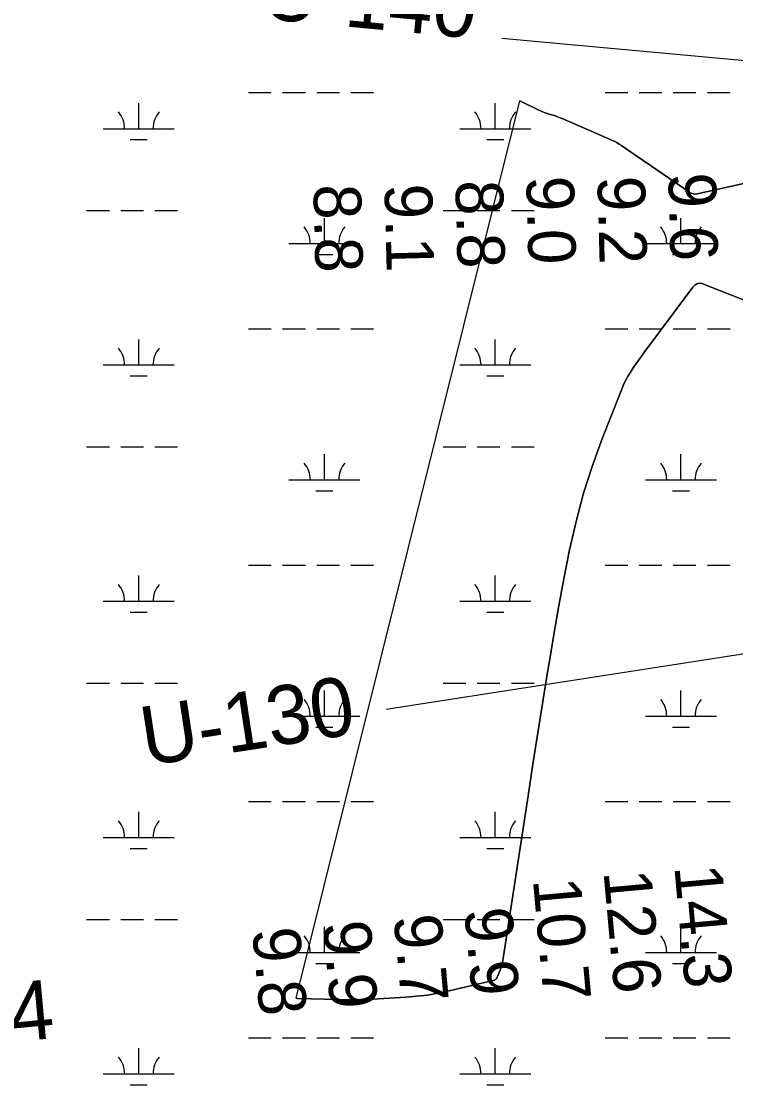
# Model space of a CAD drawing. Extents: x 3535183 to 3573198, y 534952 to 560562.
# Drawn here: x 3550386 to 3551392, y 549415 to 550912 of the extents above; entities that cross this region are included whole.
import ezdxf

# ---------------------------------------------------------------- set-up
doc = ezdxf.new("R2010")
doc.units = 0
for name, color, linetype in [('V-RIVR-RANG', 7, 'Continuous'), ('V-RIVR-RANG-IDEN', 7, 'Continuous'), ('V-TOPO-DPTH', 7, 'Continuous'), ('V-TOPO-MINR', 7, 'Continuous'), ('V-WETL-SWMP', 7, 'Continuous')]:
    doc.layers.add(name, color=color, linetype=linetype)

msp = doc.modelspace()

# ---------------------------------------------------------------- linework, layer by layer
at = {"layer": 'V-RIVR-RANG'}
for p, q in [((3551063.1, 550888.7), (3551959.3, 550806.5)), ((3550900.3, 549943.7), (3551789.6, 550082.1))]:
    msp.add_line(p, q, dxfattribs=at)
at = {"layer": 'V-TOPO-DPTH'}
for points in [[(3551428, 550510.3), (3551344.6, 550543.1), (3551341.1, 550543.7), (3551337.7, 550542.8), (3551334.6, 550540.8), (3551332.1, 550538.1), (3551263.1, 550445.8), (3551258.5, 550439.5), (3551253.9, 550433.1), (3551249.5, 550426.6), (3551245.2, 550420), (3551241.1, 550413.3), (3551237.3, 550406.5), (3551234, 550399.4), (3551230.9, 550392.2), (3551204.9, 550325.7), (3551190.8, 550287), (3551178.2, 550247.9), (3551167.6, 550208.1), (3551158.5, 550168), (3551150.5, 550127.5), (3551142.9, 550086.9), (3551135.8, 550046.3), (3551129, 550005.6), (3551127.8, 549998.8), (3551120.7, 549954.6), (3551113.7, 549910.4), (3551106.8, 549866.2), (3551099.9, 549822), (3551064.2, 549589.9), (3551063.3, 549585.3), (3551062.2, 549580.8), (3551060.6, 549576.4), (3551058.8, 549572.1), (3551055.3, 549564.4), (3551055.1, 549564), (3551053.8, 549562.7), (3551052.5, 549562.2), (3550988.7, 549547.2), (3550973.6, 549544.1), (3550958.4, 549541.4), (3550943.1, 549539.6), (3550927.7, 549538.3), (3550889.2, 549535.9), (3550875.1, 549535.2), (3550861, 549534.8), (3550846.8, 549534.7), (3550832.7, 549534.9), (3550775.1, 549536.5), (3550773.3, 549536.8), (3551088.5, 550800.4)], [(3551088.5, 550800.4), (3551114.2, 550787.8), (3551118.3, 550785.9), (3551122.4, 550784.1), (3551126.7, 550782.7), (3551131, 550781.3), (3551135.3, 550780), (3551139.6, 550778.6), (3551143.8, 550777), (3551148, 550775.3), (3551217.8, 550745.1), (3551221.3, 550743.4), (3551224.8, 550741.6), (3551228.1, 550739.6), (3551231.4, 550737.5), (3551234.7, 550735.3), (3551237.9, 550733), (3551241.1, 550730.8), (3551244.3, 550728.6), (3551327.2, 550671.6), (3551328.4, 550670.8), (3551332.4, 550669.3), (3551335.3, 550669), (3551338.2, 550669.3), (3551424.8, 550688.5)]]:
    msp.add_lwpolyline(points, dxfattribs=at)
at = {"layer": 'V-TOPO-MINR'}
for points in [[(3551424.8, 550688.5), (3551338.2, 550669.3), (3551335.3, 550669), (3551332.4, 550669.3), (3551328.4, 550670.8), (3551327.2, 550671.6), (3551244.3, 550728.6), (3551241.1, 550730.8), (3551237.9, 550733), (3551234.7, 550735.3), (3551231.4, 550737.5), (3551228.1, 550739.6), (3551224.8, 550741.6), (3551221.3, 550743.4), (3551217.8, 550745.1), (3551148, 550775.3), (3551143.8, 550777), (3551139.6, 550778.6), (3551135.3, 550780), (3551131, 550781.3), (3551126.7, 550782.7), (3551122.4, 550784.1), (3551118.3, 550785.9), (3551114.2, 550787.8), (3551088.5, 550800.4)], [(3550773.3, 549536.8), (3550775.1, 549536.5), (3550832.7, 549534.9), (3550846.8, 549534.7), (3550861, 549534.8), (3550875.1, 549535.2), (3550889.2, 549535.9), (3550927.7, 549538.3), (3550943.1, 549539.6), (3550958.4, 549541.4), (3550973.6, 549544.1), (3550988.7, 549547.2), (3551052.5, 549562.2), (3551053.8, 549562.7), (3551055.1, 549564), (3551055.3, 549564.4), (3551058.8, 549572.1), (3551060.6, 549576.4), (3551062.2, 549580.8), (3551063.3, 549585.3), (3551064.2, 549589.9), (3551099.9, 549822), (3551106.8, 549866.2), (3551113.7, 549910.4), (3551120.7, 549954.6), (3551127.8, 549998.8), (3551129, 550005.6), (3551135.8, 550046.3), (3551142.9, 550086.9), (3551150.5, 550127.5), (3551158.5, 550168), (3551167.6, 550208.1), (3551178.2, 550247.9), (3551190.8, 550287), (3551204.9, 550325.7), (3551230.9, 550392.2), (3551234, 550399.4), (3551237.3, 550406.5), (3551241.1, 550413.3), (3551245.2, 550420), (3551249.5, 550426.6), (3551253.9, 550433.1), (3551258.5, 550439.5), (3551263.1, 550445.8), (3551332.1, 550538.1), (3551334.6, 550540.8), (3551337.7, 550542.8), (3551341.1, 550543.7), (3551344.6, 550543.1), (3551428, 550510.3)]]:
    msp.add_lwpolyline(points, dxfattribs=at)
at = {"layer": 'V-WETL-SWMP'}
for p, q in [((3550706.4, 550811.9), (3550738.4, 550811.9)), ((3550754.4, 550811.9), (3550786.4, 550811.9)), ((3550802.4, 550811.9), (3550834.4, 550811.9)), ((3550850.4, 550811.9), (3550882.4, 550811.9)), ((3551208.4, 550811.9), (3551240.4, 550811.9)), ((3551256.4, 550811.9), (3551288.4, 550811.9)), ((3551304.4, 550811.9), (3551336.4, 550811.9)), ((3551352.4, 550811.9), (3551384.4, 550811.9)), ((3550551.9, 550761.2), (3550551.9, 550797.2)), ((3551053.8, 550761.2), (3551053.8, 550797.2)), ((3550501.9, 550761.2), (3550601.9, 550761.2)), ((3551003.8, 550761.2), (3551103.8, 550761.2)), ((3550539.9, 550745.8), (3550563.9, 550745.8)), ((3551041.8, 550745.8), (3551065.8, 550745.8)), ((3550478.4, 550645.8), (3550510.4, 550645.8)), ((3550526.4, 550645.8), (3550558.4, 550645.8)), ((3550574.4, 550645.8), (3550606.4, 550645.8)), ((3550813.3, 550599.3), (3550813.3, 550635.3)), ((3550980.4, 550645.8), (3551012.4, 550645.8)), ((3551028.4, 550645.8), (3551060.4, 550645.8)), ((3551076.4, 550645.8), (3551108.4, 550645.8)), ((3551315.2, 550599.3), (3551315.2, 550635.3)), ((3550763.3, 550599.3), (3550863.3, 550599.3)), ((3551265.2, 550599.3), (3551365.2, 550599.3)), ((3550801.3, 550583.9), (3550825.3, 550583.9)), ((3551303.2, 550583.9), (3551327.2, 550583.9)), ((3550706.4, 550479.3), (3550738.4, 550479.3)), ((3550754.4, 550479.3), (3550786.4, 550479.3)), ((3550802.4, 550479.3), (3550834.4, 550479.3)), ((3550850.4, 550479.3), (3550882.4, 550479.3)), ((3551208.4, 550479.3), (3551240.4, 550479.3)), ((3551256.4, 550479.3), (3551288.4, 550479.3)), ((3551304.4, 550479.3), (3551336.4, 550479.3)), ((3551352.4, 550479.3), (3551384.4, 550479.3)), ((3550551.9, 550428.5), (3550551.9, 550464.5)), ((3551053.8, 550428.5), (3551053.8, 550464.5)), ((3550501.9, 550428.5), (3550601.9, 550428.5)), ((3551003.8, 550428.5), (3551103.8, 550428.5)), ((3550539.9, 550413.1), (3550563.9, 550413.1)), ((3551041.8, 550413.1), (3551065.8, 550413.1)), ((3550478.4, 550313.1), (3550510.4, 550313.1)), ((3550526.4, 550313.1), (3550558.4, 550313.1)), ((3550574.4, 550313.1), (3550606.4, 550313.1)), ((3550980.4, 550313.1), (3551012.4, 550313.1)), ((3551028.4, 550313.1), (3551060.4, 550313.1)), ((3551076.4, 550313.1), (3551108.4, 550313.1)), ((3550813.3, 550266.7), (3550813.3, 550302.7)), ((3551315.2, 550266.7), (3551315.2, 550302.7)), ((3550763.3, 550266.7), (3550863.3, 550266.7)), ((3551265.2, 550266.7), (3551365.2, 550266.7)), ((3550801.3, 550251.2), (3550825.3, 550251.2)), ((3551303.2, 550251.2), (3551327.2, 550251.2)), ((3550706.4, 550146.6), (3550738.4, 550146.6)), ((3550754.4, 550146.6), (3550786.4, 550146.6)), ((3550802.4, 550146.6), (3550834.4, 550146.6)), ((3550850.4, 550146.6), (3550882.4, 550146.6)), ((3551208.4, 550146.6), (3551240.4, 550146.6)), ((3551256.4, 550146.6), (3551288.4, 550146.6)), ((3551304.4, 550146.6), (3551336.4, 550146.6)), ((3551352.4, 550146.6), (3551384.4, 550146.6)), ((3550551.9, 550095.9), (3550551.9, 550131.9)), ((3551053.8, 550095.9), (3551053.8, 550131.9)), ((3550501.9, 550095.9), (3550601.9, 550095.9)), ((3551003.8, 550095.9), (3551103.8, 550095.9)), ((3550539.9, 550080.4), (3550563.9, 550080.4)), ((3551041.8, 550080.4), (3551065.8, 550080.4)), ((3550478.4, 549980.4), (3550510.4, 549980.4)), ((3550526.4, 549980.4), (3550558.4, 549980.4)), ((3550574.4, 549980.4), (3550606.4, 549980.4)), ((3550980.4, 549980.4), (3551012.4, 549980.4)), ((3551028.4, 549980.4), (3551060.4, 549980.4)), ((3551076.4, 549980.4), (3551108.4, 549980.4)), ((3550813.3, 549934), (3550813.3, 549970)), ((3551315.2, 549934), (3551315.2, 549970)), ((3550763.3, 549934), (3550863.3, 549934)), ((3551265.2, 549934), (3551365.2, 549934)), ((3550801.3, 549918.6), (3550825.3, 549918.6)), ((3551303.2, 549918.6), (3551327.2, 549918.6)), ((3550706.4, 549813.9), (3550738.4, 549813.9)), ((3550754.4, 549813.9), (3550786.4, 549813.9)), ((3550802.4, 549813.9), (3550834.4, 549813.9)), ((3550850.4, 549813.9), (3550882.4, 549813.9)), ((3551208.4, 549813.9), (3551240.4, 549813.9)), ((3551256.4, 549813.9), (3551288.4, 549813.9)), ((3551304.4, 549813.9), (3551336.4, 549813.9)), ((3551352.4, 549813.9), (3551384.4, 549813.9)), ((3550551.9, 549763.2), (3550551.9, 549799.2)), ((3551053.8, 549763.2), (3551053.8, 549799.2)), ((3550501.9, 549763.2), (3550601.9, 549763.2)), ((3551003.8, 549763.2), (3551103.8, 549763.2)), ((3550539.9, 549747.7), (3550563.9, 549747.7)), ((3551041.8, 549747.7), (3551065.8, 549747.7)), ((3550478.4, 549647.7), (3550510.4, 549647.7)), ((3550526.4, 549647.7), (3550558.4, 549647.7)), ((3550574.4, 549647.7), (3550606.4, 549647.7)), ((3550980.4, 549647.7), (3551012.4, 549647.7)), ((3551028.4, 549647.7), (3551060.4, 549647.7)), ((3551076.4, 549647.7), (3551108.4, 549647.7)), ((3550813.3, 549601.3), (3550813.3, 549637.3)), ((3551315.2, 549601.3), (3551315.2, 549637.3)), ((3550763.3, 549601.3), (3550863.3, 549601.3)), ((3551265.2, 549601.3), (3551365.2, 549601.3)), ((3550801.3, 549585.9), (3550825.3, 549585.9)), ((3551303.2, 549585.9), (3551327.2, 549585.9)), ((3550551.9, 549430.5), (3550551.9, 549466.5)), ((3550706.4, 549481.2), (3550738.4, 549481.2)), ((3550754.4, 549481.2), (3550786.4, 549481.2)), ((3550802.4, 549481.2), (3550834.4, 549481.2)), ((3550850.4, 549481.2), (3550882.4, 549481.2)), ((3551053.8, 549430.5), (3551053.8, 549466.5)), ((3551208.4, 549481.2), (3551240.4, 549481.2)), ((3551256.4, 549481.2), (3551288.4, 549481.2)), ((3551304.4, 549481.2), (3551336.4, 549481.2)), ((3551352.4, 549481.2), (3551384.4, 549481.2)), ((3550501.9, 549430.5), (3550601.9, 549430.5)), ((3551003.8, 549430.5), (3551103.8, 549430.5)), ((3550539.9, 549415.1), (3550563.9, 549415.1)), ((3551041.8, 549415.1), (3551065.8, 549415.1))]:
    msp.add_line(p, q, dxfattribs=at)
for centre, start, end in [((3550496.6, 550761.7), 359.2282, 40.7718), ((3550607.1, 550761.7), 139.2282, 180.7718), ((3550998.5, 550761.7), 359.2282, 40.7718), ((3551109, 550761.7), 139.2282, 180.7718), ((3550758, 550599.8), 359.2282, 40.7718), ((3550868.5, 550599.8), 139.2282, 180.7718), ((3551260, 550599.8), 359.2282, 40.7718), ((3551370.4, 550599.8), 139.2282, 180.7718), ((3550496.6, 550429), 359.2282, 40.7718), ((3550607.1, 550429), 139.2282, 180.7718), ((3550998.5, 550429), 359.2282, 40.7718), ((3551109, 550429), 139.2282, 180.7718), ((3550758, 550267.1), 359.2282, 40.7718), ((3550868.5, 550267.1), 139.2282, 180.7718), ((3551260, 550267.1), 359.2282, 40.7718), ((3551370.4, 550267.1), 139.2282, 180.7718), ((3550496.6, 550096.3), 359.2282, 40.7718), ((3550607.1, 550096.3), 139.2282, 180.7718), ((3550998.5, 550096.3), 359.2282, 40.7718), ((3551109, 550096.3), 139.2282, 180.7718), ((3550758, 549934.5), 359.2282, 40.7718), ((3550868.5, 549934.5), 139.2282, 180.7718), ((3551260, 549934.5), 359.2282, 40.7718), ((3551370.4, 549934.5), 139.2282, 180.7718), ((3550496.6, 549763.7), 359.2282, 40.7718), ((3550607.1, 549763.7), 139.2282, 180.7718), ((3550998.5, 549763.7), 359.2282, 40.7718), ((3551109, 549763.7), 139.2282, 180.7718), ((3550758, 549601.8), 359.2282, 40.7718), ((3550868.5, 549601.8), 139.2282, 180.7718), ((3551260, 549601.8), 359.2282, 40.7718), ((3551370.4, 549601.8), 139.2282, 180.7718), ((3550496.6, 549431), 359.2282, 40.7718), ((3550607.1, 549431), 139.2282, 180.7718), ((3550998.5, 549431), 359.2282, 40.7718), ((3551109, 549431), 139.2282, 180.7718)]:
    msp.add_arc(centre, 35.2, start, end, dxfattribs=at)

# ---------------------------------------------------------------- texts
at = {"layer": 'V-RIVR-RANG'}
for s, rotation, p in [('9.6', 271.5083, (3551297.4, 550698.5)), ('9.1', 271.5083, (3550897.7, 550682.8)), ('8.8', 271.5083, (3550997.6, 550688.1)), ('9.0', 271.5083, (3551097.4, 550693.8)), ('9.2', 271.5083, (3551197.5, 550693.8)), ('8.8', 271.5083, (3550797.6, 550682.3)), ('12.6', 275.1683, (3551206.1, 549715.1)), ('14.3', 275.1683, (3551305.8, 549722.5)), ('10.7', 275.1683, (3551106.7, 549704)), ('9.9', 275.1683, (3551010.1, 549661.9)), ('9.7', 275.1683, (3550910.5, 549652.4)), ('9.8', 275.1683, (3550711.4, 549633.9)), ('9.9', 275.1683, (3550810.9, 549643.4))]:
    msp.add_text(s, height=67, rotation=rotation, dxfattribs=at).set_placement(p)
at = {"layer": 'V-RIVR-RANG-IDEN'}
for s, rotation, p in [('U-140', 354.6183, (3550723.1, 550916.4)), ('U-130', 8.7023, (3550561.2, 549863.8)), ('R-130.4', 5.3068, (3550041.9, 549444.4))]:
    msp.add_text(s, height=83, rotation=rotation, dxfattribs=at).set_placement(p)

doc.saveas('drawing.dxf')
